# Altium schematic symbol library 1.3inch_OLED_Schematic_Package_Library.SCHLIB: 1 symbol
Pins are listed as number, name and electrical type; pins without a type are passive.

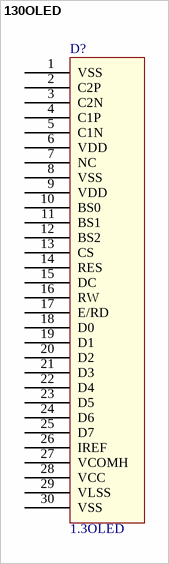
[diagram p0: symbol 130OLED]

## 130OLED
designator D?, comment 1.3OLED
footprint 096OLED
footprint 1.3OLED
pins: 1 VSS, 2 C2P, 3 C2N, 4 C1P, 5 C1N, 6 VDD, 7 NC, 8 VSS, 9 VDD, 10 BS0, 11 BS1, 12 BS2, 13 CS, 14 RES, 15 DC, 16 RW, 17 E/RD, 18 D0, 19 D1, 20 D2, 21 D3, 22 D4, 23 D5, 24 D6, 25 D7, 26 IREF, 27 VCOMH, 28 VCC, 29 VLSS, 30 VSS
